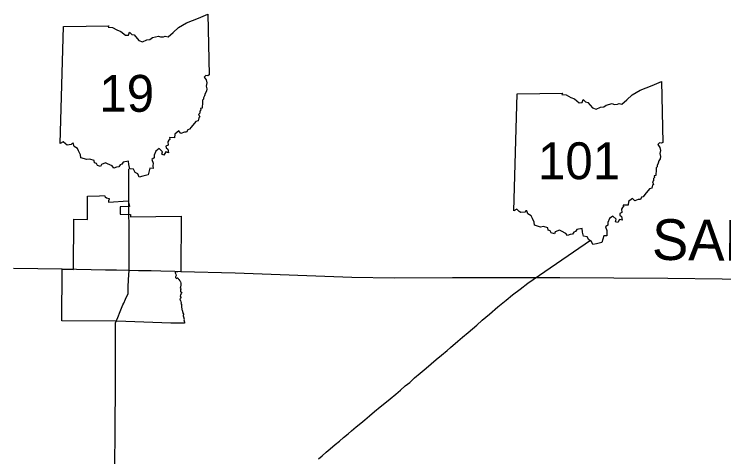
# Model space of a CAD drawing. Extents: x 0 to 882, y 0 to 440.
# Drawn here: x 381 to 468.1, y 313.4 to 367.7 of the extents above; entities that cross this region are included whole.
import ezdxf

# ---------------------------------------------------------------- set-up
doc = ezdxf.new("R2010")
doc.units = 0
for name, color, linetype in [('DV_X_Corp_Line', 7, 'Continuous'), ('GM_X_Adjacent_County_Text', 7, 'Continuous'), ('GM_X_County', 7, 'Continuous'), ('GM_X_State_Route', 7, 'Continuous'), ('PV_P_Text', 7, 'Continuous')]:
    doc.layers.add(name, color=color, linetype=linetype)

msp = doc.modelspace()

# ---------------------------------------------------------------- linework, layer by layer
at = {"layer": 'DV_X_Corp_Line'}
msp.add_lwpolyline([(390.007, 342.514), (389.991, 345.389), (391.477, 345.436), (392.074, 345.455), (392.143, 345.395), (392.181, 345.319), (392.326, 345.19), (392.659, 345.097), (392.672, 345.019), (392.563, 344.805), (392.594, 344.656), (394.975, 344.802), (395.137, 344.133), (394.008, 344.074), (394.025, 343.171), (395.295, 343.129), (395.292, 342.837), (401.502, 342.91), (401.473, 336.141), (400.745, 336.064), (400.761, 335.968), (400.862, 335.828), (400.891, 335.643), (400.809, 335.488), (400.79, 335.421), (400.827, 335.356), (400.921, 335.298), (401.046, 335.354), (401.096, 335.347), (401.175, 335.205), (401.255, 335.15), (401.304, 335.04), (401.389, 334.949), (401.417, 334.869), (401.466, 334.708), (401.442, 334.482), (401.41, 334.217), (401.368, 334.096), (401.455, 333.962), (401.414, 333.855), (401.434, 333.762), (401.413, 333.697), (401.441, 333.631), (401.52, 333.617), (401.572, 333.523), (401.45, 333.471), (401.499, 333.345), (401.423, 333.288), (401.364, 333.097), (401.378, 333.078), (401.454, 333.014), (401.461, 332.952), (401.41, 332.813), (401.351, 332.76), (401.387, 332.625), (401.43, 332.569), (401.476, 332.408), (401.509, 332.332), (401.507, 332.283), (401.468, 332.177), (401.532, 332.113), (401.519, 332.06), (401.538, 332.022), (401.534, 331.812), (401.556, 331.748), (401.595, 331.547), (401.583, 331.47), (401.613, 331.41), (401.69, 331.099), (401.69, 331.027), (401.763, 330.884), (401.746, 330.69), (401.777, 330.566), (401.853, 330.302), (401.825, 330.2), (401.909, 329.91), (401.915, 329.817), (400.235, 329.787), (393.596, 330.036), (386.838, 330.077), (386.884, 336.421), (388.272, 336.389), (388.34, 342.548)], close=True, dxfattribs=at)
at = {"layer": 'GM_X_County'}
msp.add_lwpolyline([(380.907, 336.557), (386.871, 336.466), (392.203, 336.354), (393.564, 336.325), (395.129, 336.301), (396.246, 336.276), (397.802, 336.246), (399.002, 336.206), (400.729, 336.16), (401.473, 336.141), (408.14, 335.977), (422.458, 335.425), (427.634, 335.362), (434.799, 335.397), (445.088, 335.406), (447.982, 335.381), (461.221, 335.322), (467.899, 335.229), (474.535, 335.126)], dxfattribs=at)
at = {"layer": 'GM_X_State_Route'}
msp.add_line((395.129, 336.301), (395.062, 348.747), dxfattribs=at)
for points in [[(418.337, 313.152), (418.789, 313.518), (419.28, 313.951), (419.795, 314.38), (420.408, 314.915), (420.914, 315.314), (421.429, 315.752), (421.977, 316.205), (422.425, 316.581), (422.983, 317.067), (423.551, 317.529), (424.032, 317.929), (424.633, 318.425), (425.24, 318.94), (425.937, 319.523), (426.707, 320.164), (427.16, 320.52), (427.834, 321.088), (428.407, 321.58), (429.003, 322.093), (429.551, 322.521), (430.156, 323.084), (430.85, 323.681), (431.565, 324.277), (432.197, 324.805), (432.817, 325.322), (433.473, 325.87), (434.14, 326.427), (434.559, 326.804), (435.466, 327.585), (436.015, 328.063), (436.709, 328.648), (437.27, 329.121), (437.802, 329.572), (438.461, 330.16), (439.35, 330.912), (440.384, 331.784), (441.387, 332.637), (442.175, 333.294), (443.099, 333.981), (444.072, 334.708), (451.737, 339.977)], [(395.016, 335.106), (395.016, 335.108), (395.129, 336.301)], [(394.974, 333.507), (394.98, 333.689), (394.999, 334.321), (395.015, 335.048), (395.016, 335.106)], [(393.429, 329.823), (393.739, 330.491), (394.019, 331.211), (394.356, 332.046), (394.445, 332.253), (394.652, 332.735), (394.972, 333.45), (394.973, 333.463), (394.974, 333.507)], [(393.388, 296.583), (393.45, 298.02), (393.358, 309.898), (393.373, 312.282), (393.407, 316.485), (393.437, 322.641), (393.442, 323.16), (393.435, 323.568), (393.418, 329.26), (393.416, 329.793), (393.427, 329.817), (393.429, 329.823)]]:
    msp.add_lwpolyline(points, dxfattribs=at)
at = {"layer": 'PV_P_Text'}
for p, q in [((386.647, 351.834), (387.048, 366.197)), ((386.647, 351.834), (387.048, 366.197)), ((442.341, 343.563), (442.743, 357.926)), ((442.341, 343.563), (442.743, 357.926))]:
    msp.add_line(p, q, dxfattribs=at)
for points in [[(387.048, 366.197), (392.621, 366.291), (392.534, 366.117), (393.06, 366.08), (393.619, 365.774), (394.091, 365.58), (394.669, 365.123), (395.014, 365.128), (395.161, 365.503), (395.425, 365.214), (395.74, 365.162), (396.283, 364.475), (396.731, 364.326), (397.268, 364.561), (397.67, 364.6), (397.963, 364.833), (398.728, 365.032), (398.941, 364.913), (399.346, 364.937), (399.55, 365.025), (399.903, 364.946), (400.525, 365.469), (401.164, 366.084), (402.148, 366.665), (403.619, 367.216), (404.781, 367.708), (404.949, 360.255)], [(387.048, 366.197), (392.621, 366.291), (392.534, 366.117), (393.06, 366.08), (393.619, 365.774), (394.091, 365.58), (394.669, 365.123), (395.014, 365.128), (395.161, 365.503), (395.425, 365.214), (395.74, 365.162), (396.283, 364.475), (396.731, 364.326), (397.268, 364.561), (397.67, 364.6), (397.963, 364.833), (398.728, 365.032), (398.941, 364.913), (399.346, 364.937), (399.55, 365.025), (399.903, 364.946), (400.525, 365.469), (401.164, 366.084), (402.148, 366.665), (403.619, 367.216), (404.781, 367.708), (404.949, 360.255)], [(404.949, 360.255), (404.778, 360.15), (404.51, 360.199), (404.331, 359.99), (404.553, 359.641), (404.658, 359.273), (404.565, 358.867), (404.657, 358.532), (404.594, 358.251), (404.426, 357.972), (404.368, 357.706), (404.226, 357.426), (404.238, 357.269), (404.102, 357.145), (404.126, 356.679), (404.057, 356.42), (404.081, 356.198), (403.861, 356.139), (403.911, 355.955), (403.771, 355.813), (403.801, 355.568), (403.642, 355.412), (403.796, 355.099), (403.672, 355), (403.569, 354.62), (403.286, 354.543), (402.719, 353.847), (402.519, 353.584), (402.295, 353.519), (402.171, 353.249), (401.894, 353.248), (401.476, 353.061), (401.205, 353.383), (400.731, 352.995), (400.676, 352.547), (400.077, 352.561), (400.1, 352.335), (399.966, 352.269), (399.845, 352.042), (399.915, 351.639), (399.635, 351.536), (399.669, 351.302), (399.848, 351.159), (399.928, 350.712), (399.63, 350.803), (399.386, 350.426), (399.134, 350.514), (399.217, 350.834), (398.792, 351.217), (398.39, 350.91), (398.181, 350.419), (398.179, 350.088), (397.879, 349.888), (398.071, 349.421), (398.036, 349.099), (398.042, 348.794), (397.668, 348.805), (397.441, 347.98)], [(404.949, 360.255), (404.778, 360.15), (404.51, 360.199), (404.331, 359.99), (404.553, 359.641), (404.658, 359.273), (404.565, 358.867), (404.657, 358.532), (404.594, 358.251), (404.426, 357.972), (404.368, 357.706), (404.226, 357.426), (404.238, 357.269), (404.102, 357.145), (404.126, 356.679), (404.057, 356.42), (404.081, 356.198), (403.861, 356.139), (403.911, 355.955), (403.771, 355.813), (403.801, 355.568), (403.642, 355.412), (403.796, 355.099), (403.672, 355), (403.569, 354.62), (403.286, 354.543), (402.719, 353.847), (402.519, 353.584), (402.295, 353.519), (402.171, 353.249), (401.894, 353.248), (401.476, 353.061), (401.205, 353.383), (400.731, 352.995), (400.676, 352.547), (400.077, 352.561), (400.1, 352.335), (399.966, 352.269), (399.845, 352.042), (399.915, 351.639), (399.635, 351.536), (399.669, 351.302), (399.848, 351.159), (399.928, 350.712), (399.63, 350.803), (399.386, 350.426), (399.134, 350.514), (399.217, 350.834), (398.792, 351.217), (398.39, 350.91), (398.181, 350.419), (398.179, 350.088), (397.879, 349.888), (398.071, 349.421), (398.036, 349.099), (398.042, 348.794), (397.668, 348.805), (397.441, 347.98)], [(442.743, 357.926), (448.315, 358.019), (448.228, 357.846), (448.754, 357.809), (449.313, 357.502), (449.785, 357.309), (450.363, 356.852), (450.709, 356.857), (450.855, 357.232), (451.12, 356.943), (451.434, 356.891), (451.977, 356.204), (452.425, 356.055), (452.963, 356.29), (453.364, 356.329), (453.657, 356.562), (454.422, 356.761), (454.635, 356.642), (455.04, 356.666), (455.244, 356.754), (455.597, 356.675), (456.219, 357.197), (456.859, 357.813), (457.843, 358.394), (459.313, 358.945), (460.475, 359.437), (460.643, 351.983)], [(442.743, 357.926), (448.315, 358.019), (448.228, 357.846), (448.754, 357.809), (449.313, 357.502), (449.785, 357.309), (450.363, 356.852), (450.709, 356.857), (450.855, 357.232), (451.12, 356.943), (451.434, 356.891), (451.977, 356.204), (452.425, 356.055), (452.963, 356.29), (453.364, 356.329), (453.657, 356.562), (454.422, 356.761), (454.635, 356.642), (455.04, 356.666), (455.244, 356.754), (455.597, 356.675), (456.219, 357.197), (456.859, 357.813), (457.843, 358.394), (459.313, 358.945), (460.475, 359.437), (460.643, 351.983)], [(397.441, 347.98), (396.791, 347.822), (396.34, 347.728), (396.18, 348.103), (395.858, 348.3), (395.647, 348.677), (395.184, 348.729), (395.074, 349.246), (395.022, 349.667), (394.389, 349.563), (394.215, 349.306), (393.99, 349.237), (393.859, 348.978), (393.553, 348.956), (393.224, 348.834), (393.009, 349.088), (392.47, 349.343), (392.228, 349.475), (391.721, 349.27), (391.613, 349.028), (391.21, 349.135), (391.116, 349.405), (390.872, 349.486), (390.818, 349.772), (390.297, 349.924), (389.898, 349.864), (389.194, 350.094), (389.151, 350.47), (388.912, 350.929), (388.787, 351.247), (388.342, 351.491), (388.252, 351.869), (388.11, 351.858), (387.98, 351.704), (387.486, 351.634), (387.288, 351.789), (387.012, 352.053), (386.647, 351.834)], [(397.441, 347.98), (396.791, 347.822), (396.34, 347.728), (396.18, 348.103), (395.858, 348.3), (395.647, 348.677), (395.184, 348.729), (395.074, 349.246), (395.022, 349.667), (394.389, 349.563), (394.215, 349.306), (393.99, 349.237), (393.859, 348.978), (393.553, 348.956), (393.224, 348.834), (393.009, 349.088), (392.47, 349.343), (392.228, 349.475), (391.721, 349.27), (391.613, 349.028), (391.21, 349.135), (391.116, 349.405), (390.872, 349.486), (390.818, 349.772), (390.297, 349.924), (389.898, 349.864), (389.194, 350.094), (389.151, 350.47), (388.912, 350.929), (388.787, 351.247), (388.342, 351.491), (388.252, 351.869), (388.11, 351.858), (387.98, 351.704), (387.486, 351.634), (387.288, 351.789), (387.012, 352.053), (386.647, 351.834)], [(460.643, 351.983), (460.472, 351.879), (460.205, 351.928), (460.025, 351.719), (460.247, 351.37), (460.352, 351.002), (460.259, 350.596), (460.351, 350.261), (460.289, 349.98), (460.121, 349.701), (460.063, 349.435), (459.92, 349.155), (459.932, 348.998), (459.796, 348.874), (459.821, 348.408), (459.752, 348.149), (459.775, 347.927), (459.555, 347.868), (459.605, 347.684), (459.465, 347.542), (459.495, 347.297), (459.336, 347.141), (459.49, 346.828), (459.366, 346.729), (459.263, 346.349), (458.98, 346.272), (458.413, 345.576), (458.213, 345.313), (457.989, 345.248), (457.865, 344.978), (457.589, 344.976), (457.17, 344.789), (456.899, 345.112), (456.425, 344.724), (456.371, 344.276), (455.771, 344.29), (455.794, 344.064), (455.661, 343.998), (455.539, 343.771), (455.609, 343.368), (455.329, 343.265), (455.363, 343.031), (455.543, 342.888), (455.623, 342.441), (455.324, 342.531), (455.08, 342.155), (454.829, 342.243), (454.911, 342.562), (454.486, 342.946), (454.085, 342.639), (453.875, 342.147), (453.873, 341.817), (453.574, 341.617), (453.766, 341.15), (453.73, 340.828), (453.736, 340.523), (453.362, 340.533), (453.136, 339.709)], [(460.643, 351.983), (460.472, 351.879), (460.205, 351.928), (460.025, 351.719), (460.247, 351.37), (460.352, 351.002), (460.259, 350.596), (460.351, 350.261), (460.289, 349.98), (460.121, 349.701), (460.063, 349.435), (459.92, 349.155), (459.932, 348.998), (459.796, 348.874), (459.821, 348.408), (459.752, 348.149), (459.775, 347.927), (459.555, 347.868), (459.605, 347.684), (459.465, 347.542), (459.495, 347.297), (459.336, 347.141), (459.49, 346.828), (459.366, 346.729), (459.263, 346.349), (458.98, 346.272), (458.413, 345.576), (458.213, 345.313), (457.989, 345.248), (457.865, 344.978), (457.589, 344.976), (457.17, 344.789), (456.899, 345.112), (456.425, 344.724), (456.371, 344.276), (455.771, 344.29), (455.794, 344.064), (455.661, 343.998), (455.539, 343.771), (455.609, 343.368), (455.329, 343.265), (455.363, 343.031), (455.543, 342.888), (455.623, 342.441), (455.324, 342.531), (455.08, 342.155), (454.829, 342.243), (454.911, 342.562), (454.486, 342.946), (454.085, 342.639), (453.875, 342.147), (453.873, 341.817), (453.574, 341.617), (453.766, 341.15), (453.73, 340.828), (453.736, 340.523), (453.362, 340.533), (453.136, 339.709)], [(453.136, 339.709), (452.485, 339.551), (452.034, 339.457), (451.875, 339.831), (451.552, 340.029), (451.342, 340.406), (450.878, 340.457), (450.768, 340.975), (450.716, 341.395), (450.083, 341.292), (449.909, 341.035), (449.684, 340.966), (449.553, 340.707), (449.247, 340.685), (448.918, 340.563), (448.703, 340.817), (448.164, 341.072), (447.922, 341.204), (447.416, 340.999), (447.308, 340.757), (446.905, 340.864), (446.81, 341.134), (446.566, 341.215), (446.512, 341.501), (445.991, 341.653), (445.592, 341.593), (444.889, 341.823), (444.846, 342.199), (444.606, 342.658), (444.481, 342.976), (444.036, 343.219), (443.946, 343.598), (443.804, 343.587), (443.674, 343.433), (443.18, 343.363), (442.983, 343.517), (442.706, 343.781), (442.341, 343.563)], [(453.136, 339.709), (452.485, 339.551), (452.034, 339.457), (451.875, 339.831), (451.552, 340.029), (451.342, 340.406), (450.878, 340.457), (450.768, 340.975), (450.716, 341.395), (450.083, 341.292), (449.909, 341.035), (449.684, 340.966), (449.553, 340.707), (449.247, 340.685), (448.918, 340.563), (448.703, 340.817), (448.164, 341.072), (447.922, 341.204), (447.416, 340.999), (447.308, 340.757), (446.905, 340.864), (446.81, 341.134), (446.566, 341.215), (446.512, 341.501), (445.991, 341.653), (445.592, 341.593), (444.889, 341.823), (444.846, 342.199), (444.606, 342.658), (444.481, 342.976), (444.036, 343.219), (443.946, 343.598), (443.804, 343.587), (443.674, 343.433), (443.18, 343.363), (442.983, 343.517), (442.706, 343.781), (442.341, 343.563)]]:
    msp.add_lwpolyline(points, dxfattribs=at)

# ---------------------------------------------------------------- texts
at = {"layer": 'GM_X_Adjacent_County_Text'}
msp.add_text('SANDUSKY COUNTY', height=5, rotation=359.37317, dxfattribs=at).set_placement((459.275, 337.573))
at = {"layer": 'PV_P_Text'}
for s, p in [('19', (391.445, 355.731)), ('101', (445.286, 347.459))]:
    msp.add_text(s, height=4.5281, dxfattribs=at).set_placement(p)

doc.saveas('drawing.dxf')
